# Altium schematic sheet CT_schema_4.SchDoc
size 298 x 159 mm
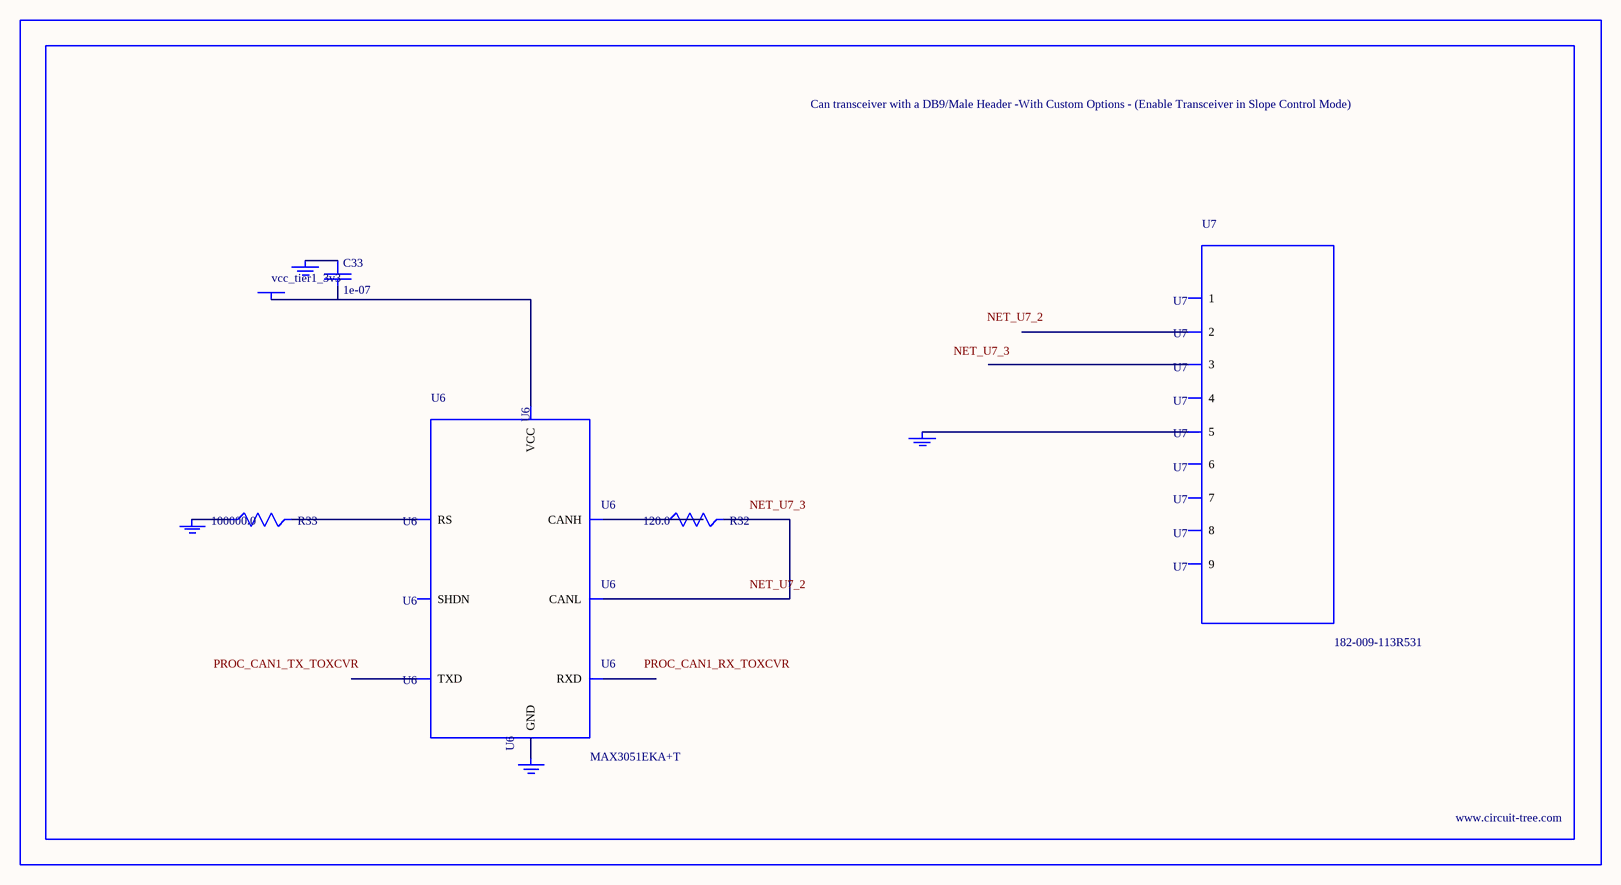
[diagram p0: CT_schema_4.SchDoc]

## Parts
BORDER3  (no value)
C33  1e-07  [C0402]
GND_INSTANCE_3_0  (no value)
GND_INSTANCE_3_1  (no value)
GND_INSTANCE_3_2  (no value)
GND_INSTANCE_3_3  (no value)
POWER_INSTANCE_3_0  vcc_tier1_3v3
R32  120.0  [R0603]
R33  100000.0  [R0603]
U6  MAX3051EKA+T  [SOT-23-8]
U7  182-009-113R531  [182-009-MALE]

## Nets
NetC33_1: C33.1 GND_INSTANCE_3_0.0(GND)
NetC33_2: C33.2 POWER_INSTANCE_3_0.0(PWR) U6.3(VCC)
NetGND_INSTANCE_3_1_0: GND_INSTANCE_3_1.0(GND) R33.1
NetGND_INSTANCE_3_2_0: GND_INSTANCE_3_2.0(GND) U6.2(GND)
NetGND_INSTANCE_3_3_0: GND_INSTANCE_3_3.0(GND) U7.5
NetR32_1: R32.1 U6.7(CANH)
NetR32_2: R32.2 U6.6(CANL)
NetR33_2: R33.2 U6.8(RS)

Not connected (* = marked no-connect by the designer): U6 1(TXD) 4(RXD) 5(SHDN); U7 1 2 3 4 6 7 8 9

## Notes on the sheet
- Labels drawn without touching a wire or pin: NET_U7_2, NET_U7_3, PROC_CAN1_RX_TOXCVR, PROC_CAN1_TX_TOXCVR

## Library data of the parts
BORDER3 = BORDER_PAGE3
C33 = C0402C104K3RACTU
GND_INSTANCE_3_0-GND_INSTANCE_3_3 = GND
POWER_INSTANCE_3_0 = PWR
R32 = RC0603JR-07120RL
R33 = RC0603JR-07100KL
